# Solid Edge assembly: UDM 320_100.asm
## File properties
Title: Zylinder
Author: ahadarics
Template: iso assembly.asm
Last saved by: ahadarics
Revision: 22
Application: Solid Edge
Username: ahadarics
Dokumentum tartalom típus: 1
Document Number: UDM 320/100
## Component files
Profilrohr 320_100.par
Mutter.par
Kolbenstange 320_100.par
Kit_1.par
Zugstange 320_100.par
Kit_2.par
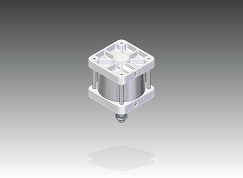
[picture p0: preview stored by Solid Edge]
